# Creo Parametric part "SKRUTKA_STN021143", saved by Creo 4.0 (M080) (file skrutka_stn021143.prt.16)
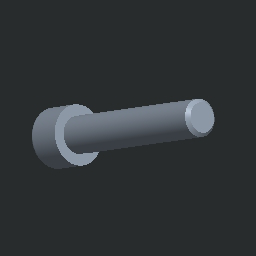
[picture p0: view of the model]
Units: Custom; MM, KILOGRAM, SECS
Materials in the file: OCEL_N

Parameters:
  KATEGORIE = "4"
  NAZOV = "SKRUTKA_STN021143"
  NORMA = "STN 02 1143"
  N1 = "021"
  N2 = "21"
  N3 = "1"
  NAZOV_1 = "START_PART_IPM"
  PTC_MATERIAL_NAME = "OCEL_N"
  PLACEMENT = "A"

Other parameters: PB, HMOTNOST, HUSTOTA, HMOTNOST_1, THREADS_PER_INCH, D15, D4, D3, D14

Created from: STN_021143_SKRUTKA_IMBUS.PRT

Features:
  1. round
  2. datum plane "DTM1"
  3. datum plane "DTM2"
  4. cut
  5. chamfer
  6. datum plane "DTM3"

Layers: BEZUGSEBENEN, NORMTEILE

Family table entries: GENERIC, SKRUTKA_M3X4, SKRUTKA_STN021143, value(d_val), 2/2, value(i_val), SKRUTKA_M3X5, SKRUTKA_STN021143, 2/2, SKRUTKA_M3X6, SKRUTKA_STN021143, 2/2, SKRUTKA_M3X8, SKRUTKA_STN021143, 2/ , 2/2, SKRUTKA_M3X10, SKRUTKA_STN021143, 2/$, 2/2, SKRUTKA_M3X12, SKRUTKA_STN021143, 2/(, 2/2, SKRUTKA_M3X16, SKRUTKA_STN021143, 2/0, 2/2, SKRUTKA_M3X20, SKRUTKA_STN021143, 2/4, 2/2, SKRUTKA_M3X25, SKRUTKA_STN021143, 2/9, 2/2, SKRUTKA_M3X30, SKRUTKA_STN021143, 2/>, 2/2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

Surfaces: 11 plane, 5 cylinder, 2 torus, 2 cone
